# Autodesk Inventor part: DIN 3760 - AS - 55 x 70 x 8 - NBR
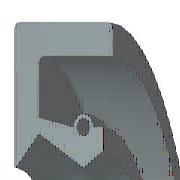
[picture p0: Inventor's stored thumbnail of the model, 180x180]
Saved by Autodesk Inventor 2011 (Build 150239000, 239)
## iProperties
Created: 2010-02
Part Number: DIN 3760 - AS - 55 x 70 x 8 - NBR
Material: Rubber
Description: Shaft Seal Ring
Document SubType Name: Modeling
Standard: DIN 3760
Designer: 129877
Standards Organization: DIN
Language: en-US
Size Designation: AS - 55 x 70 x 8 - NBR
Categories: <MemberInstance><Categories><Category DisplayName="Shaft Parts" InternalName="7f7aeb1f-a693-4053-b835-cee3144e0d98" Mnemonic="SHFT"><Category DisplayName="Seali
Density: 0.93 g/cm^3
Mass: 6.49563 g
Surface Area: 83.0172 cm^2
Volume: 6.98455 cm^3
IsCustomPart: 0
Author: 129877
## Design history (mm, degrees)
revolve "Body" stored, may be unused: angle "d17" = 90 deg
revolve "Spring1" stored, may be unused: angle "d18" = 90 deg
body "Solid1"
sketch "Sketch1"
  geometry: L1 (0, 35)-(8, 35); L2 (8, 33)-(2, 33); L3 (2, 29.5)-(5.6, 27.5); L4 (5.6, 27.5)-(0, 27.5); L5 (0, 0)-(9.586, 0) reference; L6 (5.6, 27.5)-(7.2, 28.5); L7 (0, 18)-(0, -3) reference; L8 (-1.941, 0)-(11.507, 0) reference; L9 (4.8, 29.9)-(2, 30.46); L10 (2, 30.46)-(2, 33); L11 (0, 35)-(0, 27.6); L12 (5.6, 27.5)-(0, 27.5); L13 (2, 29.5)-(0.173, 27.532); L14 (8, 35)-(8, 33); L15 (6.4, 29.9)-(7.2, 29.9); L16 (7.2, 29.9)-(7.2, 28.5); C1 r 0.52 at (5.6, 29.9); A1 r 0.8 centre (5.6, 29.9) between (6.4, 29.9) and (4.8, 29.9); A2 r 0.1 centre (0.1, 27.6) between (0, 27.6) and (0.173, 27.532); 1 further point
  constraints: 28 end point, 5 horizontal alignment, 5 point on line, 4 point on circle, 4 vertical alignment, 3 centre point, 3 tangent, 2 collinear, 2 horizontal, 2 perpendicular, 1 coincident, 1 parallel
  dimensions: "d0" = 70 diameter of L1 L5 (= SD2); "d1" = 2 distance of L1.end L2.start (= SD); "d2" = 1.04 diameter of C1 (= SPDI); "d3" = 1.6 diameter of A1 (= SPDA); "d4" = 55 diameter of L3.end L5 (= NND); "d5" = 59 diameter of L3.start L5 (= TKDM); "d7" = 60.92 diameter of L9.end L5 (= TKDM + 0.24 x SWDT); "d8" = 2 distance between parallel lines of L11 L10 (= SD); "d9" = 5.6 distance from line of L11 C1.centre (= SPDST); "d10" = 59.8 diameter of C1.centre L5 (= HLDM); "d11" = 0.1 radius of A2 (= 0.25 x LAB); "d12" = 7.2 distance between parallel lines of L11 L16 (= SDI); "d13" = 57 diameter of L6.end L5 (= ABDM); "d14" = 8 distance from line of L11 L1.end (= SWDT)
fillet "Fillet1" dims "d6" = 0.4 (= RR)
other parameters: "SD2" = 70 [user parameter; used in 1 equation term], "SWDT" = 8 [user parameter; used in 2 equation terms], "RR" = 0.4 [user parameter; used in 1 equation term], "SD" = 2 [user parameter; used in 2 equation terms], "NND" = 55 [user parameter; used in 1 equation term], "SPDA" = 1.6 [user parameter; used in 1 equation term], "SPDI" = 1.04 [user parameter; used in 1 equation term], "TKDM" = 59 [user parameter; used in 2 equation terms], "HLDM" = 59.8 [user parameter; used in 1 equation term], "ABDM" = 57 [user parameter; used in 1 equation term], "SDI" = 7.2 [user parameter; used in 1 equation term], "SPDST" = 5.6 [user parameter; used in 1 equation term], "LAB" = 0.4 [user parameter; used in 1 equation term], "d15" = 0, "d16" = 0, "d19" = 0
